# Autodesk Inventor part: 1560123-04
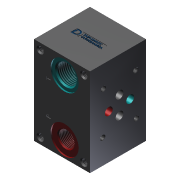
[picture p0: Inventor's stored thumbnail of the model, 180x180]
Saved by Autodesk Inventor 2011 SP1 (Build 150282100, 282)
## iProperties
Category: PARTsolutions
Company: DUPLOMATIC
Created: 2016-07
Part Number: 1560123-04
Catalog Web Link: www.cadenas.de
Description: P2D-*-Modular subplates
Vendor: DUPLOMATIC
Document SubType Name: Modeling
Designer: psAdmin
Manufacturer: DUPLOMATIC
Mass: 1425 g
Surface Area: 361.639 cm^2
Volume: 207.658 cm^3
Density: 6.86224 g/cm^3
PSOL_IDENT_0: {$CADENAS_DATA\23d-libs\duplomatic\05_subplates_and_manifolds\52000\p2d.prj},165 {VTYP=3D},{NB=15601
PSOL_IDENT_1: 23-04},{LINA=P2D-I/21},{NN=P2D-*},{DATE=20.04.2016 06:16:59},{GEOMDATE=07.11.2012 00:00:00},{VERSION=
PSOL_IDENT_2: },{LINEID=10},{LINESUBID=-1},{WBVAR=VER,GU}  {NB=1560123-04},{LINA=P2D-I/21},{KT=DUMMY},{CODE=156012
PSOL_IDENT_3: 3-04},{TIPO=P2D},{VER=I},{SER=21},{GU=},{PORT=Rear ports},{LAG=P2D-I/21},{VERS=3}
NN: P2D-*
NT: Modular subplates
NB: 1560123-04
NBSYN: $CODE.$GU.
LINA: P2D-I/21
TIPO: P2D
VER: I = intermediate with threaded fastening
SER: 21
GU: NBR
PORT: Rear ports
SUPPLIER: DUPLOMATIC
ARTICLENO: 1560123-04
BOMINFO: P2D-I/21
CREATOR: CADENAS GmbH
Title: P2D-I/21
Author: Cadenas PARTsolutions
Comments: Modular subplates
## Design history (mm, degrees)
sketch "Sketch_1"
  geometry: L1 (-27, -27)-(27, -27); L2 (27, -27)-(27, 27); L3 (27, 27)-(-27, 27); L4 (-27, 27)-(-27, -27)
  constraints: 8 end point
extrude "Extrusion1" join sketch "Sketch_1" stored distance "d0" = 85; taper "d1" = 0 deg
sketch "Sketch_2"
  geometry: L1 (-27, -8)-(-27, -27); L2 (-27, -27)-(-40.5, -27); L3 (-40.5, -27)-(-40.5, -25.7); L4 (-40.5, -25.7)-(-37.477, -25.7); L5 (-37.477, -25.7)-(-36.316, -24.538); L6 (-36.316, -24.538)-(-36.316, -8); L7 (-36.316, -8)-(-27, -8); L8 (-27, -8)-(-27, -27)
  constraints: 16 end point
revolve "Revolution1" sketch "Sketch_2" stored, may be unused: angle "d2" = 360 deg
thread "Thread1" dims "d3" = 13.338, "d4" = 0
sketch "Sketch3"
  geometry: 1 further point
hole "Hole1" sketch "Sketch3" at (29.5, 17.5) diameter "d5" = 14.95; stored, may be unused: countersink angle "d9" = 90 deg, drill point angle "d11" = 0 deg; dims "d6" = 13, "d7" = 16.662, "d8" = 2, "d10" = 35
sketch "Sketch_4"
  geometry: L1 (27, -8)-(27, -27); L2 (27, -27)-(13.5, -27); L3 (13.5, -27)-(13.5, -25.7); L4 (13.5, -25.7)-(18.669, -25.7); L5 (18.669, -25.7)-(19.525, -24.844); L6 (19.525, -24.844)-(19.525, -8); L7 (19.525, -8)-(27, -8); L8 (27, -8)-(27, -27)
  constraints: 16 end point
revolve "Revolution2" sketch "Sketch_4" stored, may be unused: angle "d12" = 360 deg
thread "Thread2" dims "d13" = 12.144, "d14" = 0
sketch "Sketch5"
  geometry: 1 further point
hole "Hole2" sketch "Sketch5" at (29.5, 67.5) diameter "d15" = 14.95; stored, may be unused: countersink angle "d19" = 90 deg, drill point angle "d21" = 0 deg; dims "d16" = 13, "d17" = 16.662, "d18" = 2, "d20" = 35
sketch "Sketch6"
  geometry: 1 further point
hole "Hole3" sketch "Sketch6" at (6, 6) diameter "d22" = 4.917; stored, may be unused: countersink angle "d26" = 90 deg, drill point angle "d28" = 120 deg; dims "d23" = 12, "d24" = 7, "d25" = 2, "d27" = 14.58058
pattern_linear "Rectangular Pattern1" dims "d31" = 42, "d34" = 73
sketch "Sketch7"
  geometry: 1 further point
hole "Hole4" sketch "Sketch7" at (6, -6) diameter "d35" = 4.917; stored, may be unused: countersink angle "d39" = 90 deg, drill point angle "d41" = 120 deg; dims "d36" = 12, "d37" = 7, "d38" = 2, "d40" = 14.58058
pattern_linear "Rectangular Pattern2" dims "d44" = 42, "d47" = 73
sketch "Sketch8"
  geometry: 1 further point
hole "Hole5" sketch "Sketch8" at (42.5, 18.2) diameter "d48" = 7.5; stored, may be unused: countersink angle "d52" = 90 deg, drill point angle "d54" = 120 deg; dims "d49" = 6, "d50" = 4, "d51" = 2, "d53" = 25.83494
sketch "Sketch9"
  geometry: 1 further point
hole "Hole6" sketch "Sketch9" at (42.5, 38.8) diameter "d55" = 7.5; stored, may be unused: countersink angle "d59" = 90 deg, drill point angle "d61" = 120 deg; dims "d56" = 6, "d57" = 4, "d58" = 2, "d60" = 25.83494
sketch "Sketch10"
  geometry: 1 further point
hole "Hole7" sketch "Sketch10" at (33.7, 28.5) diameter "d62" = 7.5; stored, may be unused: countersink angle "d66" = 90 deg, drill point angle "d68" = 120 deg; dims "d63" = 6, "d64" = 4, "d65" = 2, "d67" = 42.83494
sketch "Sketch11"
  geometry: 1 further point
hole "Hole8" sketch "Sketch11" at (51.2, 28.5) diameter "d69" = 7.5; stored, may be unused: countersink angle "d73" = 90 deg, drill point angle "d75" = 120 deg; dims "d70" = 6, "d71" = 4, "d72" = 2, "d74" = 42.83494
sketch "Sketch12"
  geometry: 1 further point
hole "Hole9" sketch "Sketch12" at (21, 13.05) diameter "d76" = 4.134; stored, may be unused: countersink angle "d80" = 90 deg, drill point angle "d82" = 120 deg; dims "d77" = 10, "d78" = 5, "d79" = 2, "d81" = 11.80662
sketch "Sketch13"
  geometry: 1 further point
hole "Hole10" sketch "Sketch13" at (61.5, 12.3) diameter "d83" = 4.134; stored, may be unused: countersink angle "d87" = 90 deg, drill point angle "d89" = 120 deg; dims "d84" = 10, "d85" = 5, "d86" = 2, "d88" = 11.80662
sketch "Sketch14"
  geometry: 1 further point
hole "Hole11" sketch "Sketch14" at (21, 44.05) diameter "d90" = 4.134; stored, may be unused: countersink angle "d94" = 90 deg, drill point angle "d96" = 120 deg; dims "d91" = 10, "d92" = 5, "d93" = 2, "d95" = 11.80662
sketch "Sketch15"
  geometry: 1 further point
hole "Hole12" sketch "Sketch15" at (61.5, 44.8) diameter "d97" = 4.134; stored, may be unused: countersink angle "d101" = 90 deg, drill point angle "d103" = 120 deg; dims "d98" = 10, "d99" = 5, "d100" = 2, "d102" = 11.80662
sketch "Sketch_14"
  geometry: L1 (-5.5, -16.5)-(-27, -16.5); L2 (-27, -16.5)-(-27, -4.5); L3 (-27, -4.5)-(-26, -4.5); L4 (-26, -4.5)-(-26, -8.169); L5 (-26, -8.169)-(-25.144, -9.025); L6 (-25.144, -9.025)-(-9.5, -9.025); L7 (-9.5, -9.025)-(-5.5, -16.5); L8 (-5.5, -16.5)-(-27, -16.5)
  constraints: 16 end point
revolve "Revolution3" sketch "Sketch_14" stored, may be unused: angle "d104" = 360 deg
thread "Thread3" dims "d105" = 12.144, "d106" = 0
sketch "Sketch_15"
  geometry: L1 (-5.5, 16.5)-(-27, 16.5); L2 (-27, 16.5)-(-27, 28.5); L3 (-27, 28.5)-(-26, 28.5); L4 (-26, 28.5)-(-26, 24.831); L5 (-26, 24.831)-(-25.144, 23.975); L6 (-25.144, 23.975)-(-9.5, 23.975); L7 (-9.5, 23.975)-(-5.5, 16.5); L8 (-5.5, 16.5)-(-27, 16.5)
  constraints: 16 end point
revolve "Revolution4" sketch "Sketch_15" stored, may be unused: angle "d107" = 360 deg
thread "Thread4" dims "d108" = 12.144, "d109" = 0
sketch "Sketch_30"
  geometry: L1 (42.5, -5)-(22.5, -5); L2 (22.5, -5)-(26.816, 2.475); L3 (26.816, 2.475)-(40.644, 2.475); L4 (40.644, 2.475)-(41.5, 3.331); L5 (41.5, 3.331)-(41.5, 7); L6 (41.5, 7)-(42.5, 7); L7 (42.5, 7)-(42.5, -5); L8 (42.5, -5)-(22.5, -5)
  constraints: 16 end point
revolve "Revolution5" sketch "Sketch_30" stored, may be unused: angle "d110" = 360 deg
thread "Thread5" dims "d111" = 12.144, "d112" = 0
sketch "Sketch_16"
  geometry: L1 (-9.422, -3.5)-(12.117, -3.5); L2 (12.117, 3)-(-9.422, 3); L3 (11.496, -2.508)-(11.868, -2.508); L4 (11.868, -2.508)-(12.052, -2.061); L5 (12.052, -2.061)-(12.833, -2.061); L6 (12.833, -2.061)-(13.012, -2.508); L7 (13.012, -2.508)-(13.387, -2.508); L8 (13.387, -2.508)-(12.654, -0.699); L9 (12.654, -0.699)-(12.245, -0.699); L10 (12.245, -0.699)-(11.496, -2.508); L11 (10.766, -2.508)-(11.358, -2.508); L12 (11.358, -2.508)-(11.358, -2.237); L13 (11.358, -2.237)-(10.812, -2.237); L14 (10.794, -0.97)-(11.358, -0.97); L15 (11.358, -0.97)-(11.358, -0.699); L16 (11.358, -0.699)-(10.764, -0.699); L17 (9.283, -1.164)-(9.283, -2.508); L18 (9.283, -2.508)-(9.614, -2.508); L19 (9.614, -2.508)-(9.614, -1.164); L20 (9.614, -1.164)-(9.283, -1.164); L21 (9.283, -0.699)-(9.283, -0.973); L22 (9.283, -0.973)-(9.614, -0.973); L23 (9.614, -0.973)-(9.614, -0.699); L24 (9.614, -0.699)-(9.283, -0.699); L25 (9.507, 0.199)-(10.098, 0.199); L26 (10.098, 0.199)-(10.098, 0.47); L27 (10.098, 0.47)-(9.553, 0.47); L28 (9.534, 1.737)-(10.098, 1.737); L29 (10.098, 1.737)-(10.098, 2.008); L30 (10.098, 2.008)-(9.504, 2.008); L31 (8.023, 2.008)-(8.023, 1.736); L32 (8.023, 1.736)-(8.354, 1.736); L33 (8.354, 1.736)-(8.354, 2.008); L34 (8.354, 2.008)-(8.023, 2.008); L35 (8.023, 1.545)-(8.023, 0.199); L36 (8.023, 0.199)-(8.354, 0.199); L37 (8.354, 0.199)-(8.354, 1.545); L38 (8.354, 1.545)-(8.023, 1.545); L39 (6.885, -0.699)-(6.885, -2.508); L40 (6.885, -2.508)-(7.205, -2.508); L41 (7.205, -2.508)-(7.205, -1.052); L42 (7.205, -1.052)-(7.726, -2.508); L43 (7.726, -2.508)-(8.062, -2.508); L44 (8.062, -2.508)-(8.583, -1.052); L45 (8.583, -1.052)-(8.583, -2.508); L46 (8.583, -2.508)-(8.903, -2.508); L47 (8.903, -2.508)-(8.903, -0.699); L48 (8.903, -0.699)-(8.415, -0.699); L49 (8.415, -0.699)-(7.902, -2.145); L50 (7.902, -2.145)-(7.373, -0.699); L51 (7.373, -0.699)-(6.885, -0.699); L52 (6.274, 2.008)-(6.274, 1.737); L53 (6.274, 1.737)-(6.879, 1.737); L54 (6.879, 1.737)-(6.879, 0.199); L55 (6.879, 0.199)-(7.21, 0.199); L56 (7.21, 0.199)-(7.21, 1.737); L57 (7.21, 1.737)-(7.823, 1.737); L58 (7.823, 1.737)-(7.823, 2.008); L59 (7.823, 2.008)-(6.274, 2.008); L60 (4.799, -2.508)-(5.17, -2.508); L61 (5.17, -2.508)-(5.355, -2.061); L62 (5.355, -2.061)-(6.136, -2.061); L63 (6.136, -2.061)-(6.315, -2.508); L64 (6.315, -2.508)-(6.689, -2.508)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; A1 r 3.25 centre (12.117, -0.25) between (12.117, -3.5) and (12.117, 3); A2 r 3.9 centre (-11.578, -0.25) between (-9.422, -3.5) and (-9.422, 3); A3 r 1.348 centre (11.244, -1.62) between (10.001, -1.096) and (9.947, -1.989); A4 r 0.901 centre (10.807, -1.719) between (9.947, -1.989) and (10.132, -2.316); A5 r 0.709 centre (10.607, -1.789) between (10.132, -2.316) and (10.476, -2.487); A6 r 1.887 centre (10.761, -0.621) between (10.476, -2.487) and (10.766, -2.508); A7 r 1.097 centre (10.812, -1.14) between (10.555, -2.206) and (10.812, -2.237); A8 r 0.418 centre (10.696, -1.813) between (10.422, -2.129) and (10.555, -2.206); A9 r 0.377 centre (10.667, -1.842) between (10.295, -1.905) and (10.422, -2.129); A10 r 1.462 centre (11.722, -1.588) between (10.274, -1.387) and (10.295, -1.905); A11 r 0.615 centre (10.885, -1.459) between (10.376, -1.114) and (10.274, -1.387); A12 r 0.426 centre (10.688, -1.404) between (10.597, -0.987) and (10.376, -1.114); A13 r 2.262 centre (10.892, -3.23) between (10.794, -0.97) and (10.597, -0.987); A14 r 1.706 centre (10.766, -2.405) between (10.764, -0.699) and (10.504, -0.719); A15 r 0.6 centre (10.568, -1.316) between (10.504, -0.719) and (10.254, -0.805); A16 r 0.839 centre (10.745, -1.485) between (10.254, -0.805) and (10.001, -1.096); A17 r 1.348 centre (9.984, 1.087) between (8.742, 1.611) and (8.688, 0.718); A18 r 0.901 centre (9.547, 0.989) between (8.688, 0.718) and (8.872, 0.392); A19 r 0.709 centre (9.348, 0.918) between (8.872, 0.392) and (9.217, 0.221); A20 r 1.887 centre (9.502, 2.086) between (9.217, 0.221) and (9.507, 0.199); A21 r 1.097 centre (9.553, 1.568) between (9.295, 0.501) and (9.553, 0.47); A22 r 0.418 centre (9.437, 0.894) between (9.163, 0.579) and (9.295, 0.501); A23 r 0.377 centre (9.407, 0.866) between (9.035, 0.803) and (9.163, 0.579); A24 r 1.462 centre (10.463, 1.119) between (9.015, 1.32) and (9.035, 0.803); A25 r 0.615 centre (9.625, 1.248) between (9.116, 1.593) and (9.015, 1.32); A26 r 0.426 centre (9.429, 1.304) between (9.338, 1.72) and (9.116, 1.593); A27 r 2.262 centre (9.632, -0.522) between (9.534, 1.737) and (9.338, 1.72); A28 r 1.706 centre (9.507, 0.303) between (9.504, 2.008) and (9.245, 1.988); A29 r 0.6 centre (9.309, 1.392) between (9.245, 1.988) and (8.994, 1.903); A30 r 0.839 centre (9.486, 1.222) between (8.994, 1.903) and (8.742, 1.611); A31 r 1.116 centre (1.17, -2.087) between (1.297, -0.978) and (1.166, -0.97); A32 r 0.454 centre (1.234, -1.427) between (1.541, -1.092) and (1.297, -0.978); A33 r 0.992 centre (0.698, -1.615) between (1.689, -1.583) and (1.541, -1.092); A34 r 1.21 centre (0.48, -1.568) between (1.576, -2.08) and (1.689, -1.583); A35 r 0.416 centre (1.256, -1.815) between (1.361, -2.217) and (1.576, -2.08); A36 r 1.083 centre (1.153, -1.155) between (1.177, -2.237) and (1.361, -2.217); A37 r 3.457 centre (1.169, 0.949) between (1.161, -2.508) and (1.422, -2.499); A38 r 0.716 centre (1.36, -1.785) between (1.422, -2.499) and (1.742, -2.392); A39 r 0.46 centre (1.485, -2.01) between (1.742, -2.392) and (1.893, -2.222); A40 r 1.26 centre (0.792, -1.611) between (1.893, -2.222) and (2.051, -1.57); A41 r 1.248 centre (0.803, -1.605) between (2.051, -1.57) and (1.847, -0.921); A42 r 0.492 centre (1.455, -1.219) between (1.847, -0.921) and (1.514, -0.73); A43 r 3.717 centre (1.02, -4.414) between (1.514, -0.73) and (1.147, -0.699); A44 r 1.301 centre (1.624, 1.101) between (0.444, 1.651) and (0.402, 0.652); A45 r 0.845 centre (1.2, 0.931) between (0.402, 0.652) and (0.488, 0.476); A46 r 0.529 centre (0.925, 0.774) between (0.488, 0.476) and (0.682, 0.304); A47 r 1.143 centre (1.2, 1.323) between (0.682, 0.304) and (1.799, 0.35); A48 r 0.411 centre (1.586, 0.702) between (1.799, 0.35) and (1.967, 0.547); A49 r 1.422 centre (0.665, 1.119) between (1.967, 0.547) and (2.016, 1.563); A50 r 0.471 centre (1.562, 1.437) between (2.016, 1.563) and (1.934, 1.726); A51 r 0.532 centre (1.489, 1.434) between (1.934, 1.726) and (1.743, 1.902); A52 r 1.019 centre (1.252, 1.009) between (1.743, 1.902) and (1.226, 2.027); A53 r 1.388 centre (1.257, 0.639) between (1.226, 2.027) and (0.721, 1.92); A54 r 0.675 centre (1.033, 1.322) between (0.721, 1.92) and (0.444, 1.651); A55 r 1.477 centre (0.538, 0.931) between (-0.938, 0.953) and (-0.893, 0.566); A56 r 0.405 centre (-0.502, 0.67) between (-0.893, 0.566) and (-0.773, 0.37); A57 r 0.708 centre (-0.307, 0.904) between (-0.773, 0.37) and (-0.551, 0.239); A58 r 1.672 centre (-0.189, 1.871) between (-0.551, 0.239) and (-0.173, 0.199); A59 r 1.417 centre (-0.096, 1.888) between (-0.383, 0.499) and (-0.125, 0.47); A60 r 0.235 centre (-0.347, 0.732) between (-0.521, 0.573) and (-0.383, 0.499); A61 r 0.279 centre (-0.312, 0.758) between (-0.581, 0.687) and (-0.521, 0.573); A62 r 1.466 centre (0.858, 0.962) between (-0.608, 0.972) and (-0.581, 0.687); A63 r 1.301 centre (-0.326, -1.607) between (-1.506, -1.057) and (-1.548, -2.056); A64 r 0.845 centre (-0.75, -1.776) between (-1.548, -2.056) and (-1.462, -2.232)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
  constraints: 322 end point, 278 point on circle, 139 centre point
extrude "Extrusion2" cut sketch "Sketch_16" distance "d113" = 0.5; taper "d114" = 0 deg
sketch "Sketch_17"
  geometry: A1 r 1.562 centre (-4.673, -1.589) between (-6.223, -1.401) and (-6.199, -1.919); A2 r 0.482 centre (-5.731, -1.806) between (-6.199, -1.919) and (-6.075, -2.144); A3 r 0.667 centre (-5.693, -1.597) between (-6.075, -2.144) and (-5.712, -2.264); A4 r 0.666 centre (-5.728, -1.598) between (-5.712, -2.264) and (-5.354, -2.149); A5 r 0.436 centre (-5.654, -1.833) between (-5.354, -2.149) and (-5.228, -1.925); A6 r 1.467 centre (-6.66, -1.606) between (-5.228, -1.925) and (-5.23, -1.279); A7 r 0.378 centre (-5.602, -1.345) between (-5.23, -1.279) and (-5.358, -1.056); A8 r 0.602 centre (-5.71, -1.545) between (-5.358, -1.056) and (-6.083, -1.072); A9 r 0.296 centre (-5.89, -1.297) between (-6.083, -1.072) and (-6.16, -1.176); A10 r 0.63 centre (-5.596, -1.457) between (-6.16, -1.176) and (-6.223, -1.401)
  constraints: 20 point on circle, 10 centre point
extrude "Extrusion3" cut sketch "Sketch_17" distance "d115" = 0.5; taper "d116" = 0 deg
sketch "Sketch_18"
  geometry: A1 r 1.562 centre (2.246, 1.119) between (0.696, 1.306) and (0.72, 0.788); A2 r 0.482 centre (1.189, 0.901) between (0.72, 0.788) and (0.845, 0.563); A3 r 0.667 centre (1.227, 1.11) between (0.845, 0.563) and (1.207, 0.443); A4 r 0.666 centre (1.191, 1.109) between (1.207, 0.443) and (1.565, 0.558); A5 r 0.436 centre (1.266, 0.875) between (1.565, 0.558) and (1.692, 0.782); A6 r 1.467 centre (0.259, 1.101) between (1.692, 0.782) and (1.69, 1.428); A7 r 0.378 centre (1.318, 1.362) between (1.69, 1.428) and (1.561, 1.651); A8 r 0.602 centre (1.21, 1.162) between (1.561, 1.651) and (0.837, 1.635); A9 r 0.296 centre (1.03, 1.411) between (0.837, 1.635) and (0.759, 1.531); A10 r 0.63 centre (1.323, 1.251) between (0.759, 1.531) and (0.696, 1.306)
  constraints: 20 point on circle, 10 centre point
extrude "Extrusion4" cut sketch "Sketch_18" distance "d117" = 0.5; taper "d118" = 0 deg
sketch "Sketch_19"
  geometry: A1 r 1.562 centre (0.296, -1.589) between (-1.254, -1.401) and (-1.23, -1.919); A2 r 0.482 centre (-0.761, -1.806) between (-1.23, -1.919) and (-1.105, -2.144); A3 r 0.667 centre (-0.723, -1.597) between (-1.105, -2.144) and (-0.743, -2.264); A4 r 0.666 centre (-0.759, -1.598) between (-0.743, -2.264) and (-0.385, -2.149); A5 r 0.436 centre (-0.684, -1.833) between (-0.385, -2.149) and (-0.258, -1.925); A6 r 1.467 centre (-1.691, -1.606) between (-0.258, -1.925) and (-0.26, -1.279); A7 r 0.378 centre (-0.632, -1.345) between (-0.26, -1.279) and (-0.389, -1.056); A8 r 0.602 centre (-0.74, -1.545) between (-0.389, -1.056) and (-1.113, -1.072); A9 r 0.296 centre (-0.92, -1.297) between (-1.113, -1.072) and (-1.191, -1.176); A10 r 0.63 centre (-0.627, -1.457) between (-1.191, -1.176) and (-1.254, -1.401)
  constraints: 20 point on circle, 10 centre point
extrude "Extrusion5" cut sketch "Sketch_19" distance "d119" = 0.5; taper "d120" = 0 deg
sketch "Sketch_20"
  geometry: L1 (5.23, 0.918)-(5.834, 0.918); L2 (5.834, 0.918)-(5.536, 1.694); L3 (5.536, 1.694)-(5.23, 0.918)
  constraints: 6 end point
extrude "Extrusion6" cut sketch "Sketch_20" distance "d121" = 0.5; taper "d122" = 0 deg
sketch "Sketch_21"
  geometry: L1 (5.442, -1.79)-(6.047, -1.79); L2 (6.047, -1.79)-(5.748, -1.014); L3 (5.748, -1.014)-(5.442, -1.79)
  constraints: 6 end point
extrude "Extrusion7" cut sketch "Sketch_21" distance "d123" = 0.5; taper "d124" = 0 deg
sketch "Sketch_22"
  geometry: L1 (12.139, -1.79)-(12.744, -1.79); L2 (12.744, -1.79)-(12.445, -1.014); L3 (12.445, -1.014)-(12.139, -1.79)
  constraints: 6 end point
extrude "Extrusion8" cut sketch "Sketch_22" distance "d125" = 0.5; taper "d126" = 0 deg
sketch "Sketch_23"
  geometry: L1 (-27, 27)-(-27, -27); L2 (-27, -27)-(27, -27); L3 (27, -27)-(27, 27); L4 (27, 27)-(-27, 27); L5 (-9.422, -3.5)-(12.117, -3.5); L6 (12.117, 3)-(-9.422, 3); A1 r 3.25 centre (12.117, -0.25) between (12.117, -3.5) and (12.117, 3); A2 r 3.9 centre (-11.578, -0.25) between (-9.422, -3.5) and (-9.422, 3)
  constraints: 12 end point, 4 point on circle, 2 centre point
extrude "Extrusion9" cut sketch "Sketch_23" distance "d127" = 0.5; taper "d128" = 0 deg
sketch "Sketch_24"
  geometry: L1 (-27, 27)-(-27, -27); L2 (-27, -27)-(27, -27); L3 (27, -27)-(27, 27); L4 (27, 27)-(-27, 27); L5 (-9.422, -3.5)-(12.117, -3.5); L6 (12.117, 3)-(-9.422, 3); A1 r 3.25 centre (12.117, -0.25) between (12.117, -3.5) and (12.117, 3); A2 r 3.9 centre (-11.578, -0.25) between (-9.422, -3.5) and (-9.422, 3)
  constraints: 12 end point, 4 point on circle, 2 centre point
extrude "Extrusion10" join sketch "Sketch_24" distance "d129" = 0.5; taper "d130" = 0 deg
sketch "Sketch_25"
  geometry: L1 (-15.36, 1.7)-(-12.11, 1.7); L2 (-12.11, -2.2)-(-14.06, -2.2); L3 (-14.06, -2.2)-(-12.723, 1.109); L4 (-12.723, 1.109)-(-15.36, 1.109); L5 (-15.36, 1.109)-(-15.36, -3.5); L6 (-15.36, -3.5)-(-12.11, -3.5); L7 (-12.11, 3)-(-14.835, 3); L8 (-14.835, 3)-(-15.36, 1.7); A1 r 1.95 centre (-12.11, -0.25) between (-12.11, -2.2) and (-12.11, 1.7); A2 r 3.25 centre (-12.11, -0.25) between (-12.11, -3.5) and (-12.11, 3)
  constraints: 16 end point, 4 point on circle, 2 centre point
extrude "Extrusion11" cut sketch "Sketch_25" distance "d131" = 0.5; taper "d132" = 0 deg
sketch "Sketch_26"
  geometry: L1 (9.125, 17)-(10.5, 17); L2 (10.5, 17)-(10.5, 21); L3 (10.5, 21)-(9.125, 21); L4 (9.125, 19.25)-(10, 19.25); L5 (10, 19.25)-(10, 20.5); L6 (10, 20.5)-(9.125, 20.5); L7 (9.125, 17.5)-(10, 17.5); L8 (10, 17.5)-(10, 18.75); L9 (10, 18.75)-(9.125, 18.75); A1 r 1.125 centre (9.125, 18.125) between (8.418, 19) and (9.125, 17); A2 r 1.125 centre (9.125, 19.875) between (9.125, 21) and (8.418, 19); A3 r 0.625 centre (9.125, 19.875) between (9.125, 20.5) and (9.125, 19.25); A4 r 0.625 centre (9.125, 18.125) between (9.125, 18.75) and (9.125, 17.5)
  constraints: 18 end point, 8 point on circle, 4 centre point
extrude "Extrusion12" cut sketch "Sketch_26" distance "d133" = 0.5; taper "d134" = 0 deg
sketch "Sketch_27"
  geometry: L1 (-10.5, 17)-(-9.985, 17); L2 (-9.985, 17)-(-9.61, 18.5); L3 (-9.61, 18.5)-(-8.89, 18.5); L4 (-8.89, 18.5)-(-8.515, 17); L5 (-8.515, 17)-(-8, 17); L6 (-8, 17)-(-9, 21); L7 (-9, 21)-(-9.5, 21); L8 (-9.5, 21)-(-10.5, 17); L9 (-9.485, 19)-(-9.015, 19); L10 (-9.015, 19)-(-9.25, 19.938); L11 (-9.25, 19.938)-(-9.485, 19)
  constraints: 22 end point
extrude "Extrusion13" cut sketch "Sketch_27" distance "d135" = 0.5; taper "d136" = 0 deg
sketch "Sketch_28"
  geometry: L1 (-12.75, 14.875)-(-12.75, 15.75); L2 (-12.75, 15.75)-(-11, 15.75); L3 (-11, 15.75)-(-11, 16.25); L4 (-11, 16.25)-(-15, 16.25); L5 (-15, 16.25)-(-15, 14.875); L6 (-14.5, 15.75)-(-14.5, 14.875); L7 (-13.25, 14.875)-(-13.25, 15.75); L8 (-13.25, 15.75)-(-14.5, 15.75); A1 r 1.125 centre (-13.875, 14.875) between (-15, 14.875) and (-12.75, 14.875); A2 r 0.625 centre (-13.875, 14.875) between (-14.5, 14.875) and (-13.25, 14.875)
  constraints: 16 end point, 4 point on circle, 2 centre point
extrude "Extrusion14" cut sketch "Sketch_28" distance "d137" = 0.5; taper "d138" = 0 deg
sketch "Sketch_29"
  geometry: L1 (-15, -17.5)-(-14.5, -17.5); L2 (-14.5, -17.5)-(-14.5, -16.5); L3 (-14.5, -16.5)-(-11, -16.5); L4 (-11, -16.5)-(-11, -16); L5 (-11, -16)-(-14.5, -16); L6 (-14.5, -16)-(-14.5, -15); L7 (-14.5, -15)-(-15, -15); L8 (-15, -15)-(-15, -17.5)
  constraints: 16 end point
extrude "Extrusion15" cut sketch "Sketch_29" distance "d139" = 0.5; taper "d140" = 0 deg
sketch "Sketch_31"
  geometry: L1 (-11.275, 4.95)-(-10.4, 4.95); L2 (-10.4, 4.95)-(-10.4, 3.2); L3 (-10.4, 3.2)-(-9.9, 3.2); L4 (-9.9, 3.2)-(-9.9, 7.2); L5 (-9.9, 7.2)-(-11.275, 7.2); L6 (-11.275, 5.45)-(-10.4, 5.45); L7 (-10.4, 5.45)-(-10.4, 6.7); L8 (-10.4, 6.7)-(-11.275, 6.7); A1 r 1.125 centre (-11.275, 6.075) between (-11.275, 7.2) and (-11.275, 4.95); A2 r 0.625 centre (-11.275, 6.075) between (-11.275, 6.7) and (-11.275, 5.45)
  constraints: 16 end point, 4 point on circle, 2 centre point
extrude "Extrusion16" cut sketch "Sketch_31" distance "d141" = 0.5; taper "d142" = 0 deg
body "Solid1"
